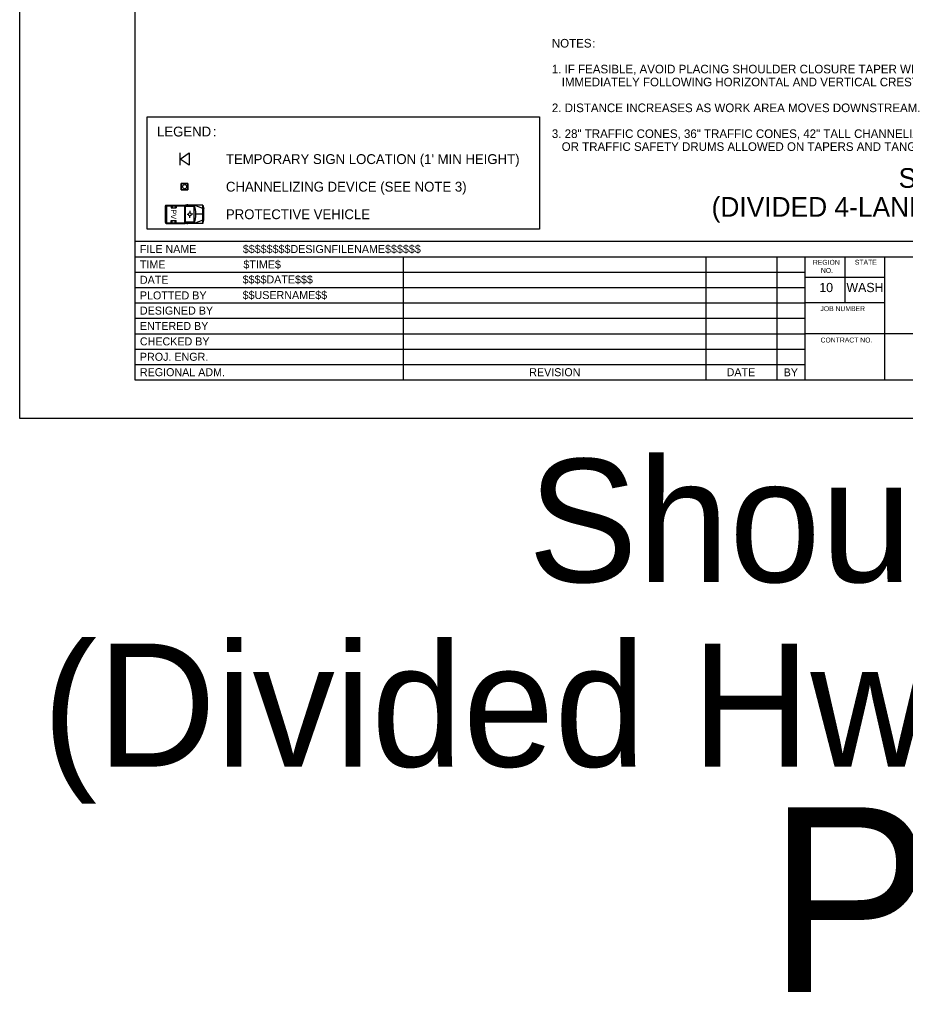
# Model space of a CAD drawing. Extents: x 99999.1 to 100055.7, y 99995 to 100010.7.
# Drawn here: x 99999.06 to 100006.26, y 99995.01 to 100002.93 of the extents above; entities that cross this region are included whole.
import ezdxf

# ---------------------------------------------------------------- set-up
doc = ezdxf.new("R2010")
doc.units = 0
for name, color, linetype in [('SH_DE_DetailHeading1Text', 7, 'Continuous'), ('SH_GI_GeneralNotesBodyText', 7, 'Continuous'), ('SH_GI_PlotLimits', 7, 'Continuous'), ('SH_GI_SheetBorder', 7, 'Continuous'), ('SH_GI_SheetLocationText', 7, 'Continuous'), ('SH_GI_SheetTextInCells', 7, 'Continuous'), ('SH_GI_TitleBlockText', 7, 'Continuous'), ('TR_WZ_PortableSignMountBlk-Wht', 7, 'Continuous'), ('TR_WZ_ProtectiveVehicle', 7, 'Continuous'), ('TR_WZ_TrafficCone', 7, 'Continuous'), ('TR_WZ_WorkZoneTextCurrent', 7, 'Continuous')]:
    doc.layers.add(name, color=color, linetype=linetype)

msp = doc.modelspace()

# ---------------------------------------------------------------- linework, layer by layer
at = {"layer": 'SH_GI_PlotLimits'}
msp.add_lwpolyline([(99999.0625, 99999.6875), (100016.0625, 99999.6875), (100016.0625, 100010.6875), (99999.0625, 100010.6875)], close=True, dxfattribs=at)
at = {"layer": 'SH_GI_SheetBorder'}
for p, q in [((100000, 100010.375), (100000, 100000)), ((100000, 100001.1259), (100015.75, 100001.1259)), ((100000, 100001.0008), (100007.4566, 100001.0008)), ((100002.179, 100001.0008), (100002.179, 100000)), ((100004.641, 100001.0008), (100004.641, 100000)), ((100005.2164, 100001.0008), (100005.2164, 100000)), ((100005.4451, 100001.0008), (100005.4451, 100000)), ((100005.7719, 100000.6255), (100005.7719, 100001.0008)), ((100006.0956, 100000), (100006.0956, 100001.0008)), ((100000, 100000.8757), (100002.1821, 100000.8757)), ((100002.1821, 100000.8757), (100005.4466, 100000.8757)), ((100006.0958, 100000.831), (100005.4466, 100000.831)), ((100000, 100000.7506), (100002.1821, 100000.7506)), ((100002.1821, 100000.7506), (100005.4466, 100000.7506)), ((100000, 100000.6255), (100005.4466, 100000.6255)), ((100006.0958, 100000.6255), (100005.4466, 100000.6255)), ((100000, 100000.5004), (100005.4466, 100000.5004)), ((100000, 100000.3753), (100005.4466, 100000.3753)), ((100007.4566, 100000.3753), (100005.4466, 100000.3753)), ((100000, 100000.2502), (100005.4466, 100000.2502)), ((100000, 100000.1251), (100005.4466, 100000.1251)), ((100000, 100000), (100015.75, 100000))]:
    msp.add_line(p, q, dxfattribs=at)
at = {"layer": 'TR_WZ_PortableSignMountBlk-Wht'}
msp.add_line((100000.3682, 100001.7439), (100000.3682, 100001.8439), dxfattribs=at)
msp.add_lwpolyline([(100000.3682, 100001.7938), (100000.44, 100001.8439), (100000.44, 100001.7439)], close=True, dxfattribs=at)
at = {"layer": 'TR_WZ_ProtectiveVehicle'}
for p, q in [((100000.248, 100001.2779), (100000.248, 100001.4138)), ((100000.2514, 100001.4184), (100000.2547, 100001.4184)), ((100000.2547, 100001.2733), (100000.2547, 100001.4184)), ((100000.2552, 100001.4208), (100000.4095, 100001.4208)), ((100000.2552, 100001.2708), (100000.2552, 100001.4208)), ((100000.2596, 100001.2768), (100000.2596, 100001.4149)), ((100000.2596, 100001.4149), (100000.4052, 100001.4149)), ((100000.2944, 100001.4149), (100000.2944, 100001.3976)), ((100000.2944, 100001.3976), (100000.3356, 100001.3976)), ((100000.3026, 100001.4149), (100000.3026, 100001.3976)), ((100000.3281, 100001.4149), (100000.3281, 100001.3976)), ((100000.3356, 100001.4149), (100000.3356, 100001.3976)), ((100000.4052, 100001.2768), (100000.4052, 100001.4149)), ((100000.4095, 100001.2708), (100000.4095, 100001.4208)), ((100000.4116, 100001.2708), (100000.4116, 100001.4208)), ((100000.5533, 100001.4208), (100000.4116, 100001.4208)), ((100000.4811, 100001.4092), (100000.4116, 100001.4092)), ((100000.4309, 100001.423), (100000.4224, 100001.423)), ((100000.4737, 100001.4092), (100000.4811, 100001.4208)), ((100000.4811, 100001.2708), (100000.4811, 100001.4208)), ((100000.4824, 100001.2708), (100000.4824, 100001.4208)), ((100000.5533, 100001.3934), (100000.4824, 100001.4208)), ((100000.5533, 100001.2708), (100000.5533, 100001.4208)), ((100000.5533, 100001.4208), (100000.5602, 100001.3906)), ((100000.5602, 100001.3011), (100000.5602, 100001.3906)), ((100000.248, 100001.3564), (100000.2547, 100001.3536)), ((100000.248, 100001.3353), (100000.2547, 100001.3381)), ((100000.2498, 100001.3458), (100000.2529, 100001.3458)), ((100000.2514, 100001.3437), (100000.2514, 100001.348)), ((100000.424, 100001.3464), (100000.4352, 100001.3461)), ((100000.4366, 100001.3461), (100000.4366, 100001.3461)), ((100000.4466, 100001.3747), (100000.4468, 100001.3634)), ((100000.4471, 100001.3161), (100000.4471, 100001.3282)), ((100000.4698, 100001.3457), (100000.4603, 100001.3458)), ((100000.5533, 100001.3458), (100000.4963, 100001.3458)), ((100000.5533, 100001.2708), (100000.5602, 100001.3011)), ((100000.2514, 100001.2733), (100000.2547, 100001.2733)), ((100000.2552, 100001.2708), (100000.4095, 100001.2708)), ((100000.2596, 100001.2768), (100000.4052, 100001.2768)), ((100000.2944, 100001.2941), (100000.3356, 100001.2941)), ((100000.2944, 100001.2768), (100000.2944, 100001.2941)), ((100000.3026, 100001.2768), (100000.3026, 100001.2941)), ((100000.3281, 100001.2768), (100000.3281, 100001.2941)), ((100000.3356, 100001.2768), (100000.3356, 100001.2941)), ((100000.4811, 100001.2825), (100000.4116, 100001.2825)), ((100000.5533, 100001.2708), (100000.4116, 100001.2708)), ((100000.4309, 100001.2687), (100000.4224, 100001.2687)), ((100000.4811, 100001.2708), (100000.4721, 100001.2825)), ((100000.5533, 100001.2983), (100000.4824, 100001.2708))]:
    msp.add_line(p, q, dxfattribs=at)
for centre, major_axis, start_param, end_param in [((100000.2514, 100001.4138), (0, 0.00458), 0, 1.570796), ((100000.3812, 100001.3459), (0, 0.1574), 4.215667, 5.208926), ((100000.2514, 100001.2779), (0, -0.00458), 4.712389, 6.283185)]:
    msp.add_ellipse(centre, major_axis=major_axis, ratio=0.73155, start_param=start_param, end_param=end_param, dxfattribs=at)
for centre, major_axis in [((100000.2514, 100001.3458), (0, -0.00211)), ((100000.4471, 100001.3458), (0, -0.0144))]:
    msp.add_ellipse(centre, major_axis=major_axis, ratio=0.73155, dxfattribs=at)
at = {"layer": 'TR_WZ_TrafficCone'}
for points in [[(100000.4308, 100001.5966), (100000.4308, 100001.5432), (100000.3775, 100001.5432), (100000.3775, 100001.5966), (100000.4308, 100001.5966)], [(100000.3775, 100001.5966), (100000.3775, 100001.5432), (100000.4308, 100001.5432), (100000.4308, 100001.5966), (100000.3775, 100001.5966)]]:
    msp.add_lwpolyline(points, dxfattribs=at)
msp.add_circle((100000.4041, 100001.5699), 0.0167, dxfattribs=at)
at = {"layer": 'TR_WZ_WorkZoneTextCurrent'}
msp.add_lwpolyline([(100000.1, 100002.1379), (100003.2886, 100002.1379), (100003.2886, 100001.2259), (100000.1, 100001.2259)], close=True, dxfattribs=at)

# ---------------------------------------------------------------- texts
at = {"layer": 'SH_DE_DetailHeading1Text'}
for s, p in [('SHOULDER CLOSURE', (100006.2068, 100001.5606)), ('(DIVIDED 4-LANE HIGHWAYS, 40 MPH OR LESS)', (100004.6868, 100001.3259))]:
    msp.add_text(s, height=0.16, rotation=360, dxfattribs=at).set_placement(p)
at = {"layer": 'SH_GI_GeneralNotesBodyText'}
for s, p in [('NOTES', (100003.3886, 100002.7006)), (':', (100003.7161, 100002.7006)), ('1. IF FEASIBLE, AVOID PLACING SHOULDER CLOSURE TAPER WITHIN OR ', (100003.3886, 100002.4906)), ('IMMEDIATELY FOLLOWING HORIZONTAL AND VERTICAL CREST CURVES.', (100003.4686, 100002.3856)), ('2. DISTANCE INCREASES AS WORK AREA MOVES DOWNSTREAM.', (100003.3886, 100002.1756)), ('3. 28" TRAFFIC CONES, 36" TRAFFIC CONES, 42" TALL CHANNELIZING DEVICES, ', (100003.3886, 100001.9656)), ('OR TRAFFIC SAFETY DRUMS ALLOWED ON TAPERS AND TANGENTS.', (100003.4686, 100001.8606))]:
    msp.add_text(s, height=0.07, rotation=360, dxfattribs=at).set_placement(p)
at = {"layer": 'SH_GI_SheetLocationText'}
for s, height, p in [('Shoulder Closure', 1, (100003.1945, 99998.3571)), ('(Divided Hwy, 40 mph & Less)', 1, (99999.2479, 99996.8571)), ('Plot 1', 1.5, (100005.1422, 99995.0267))]:
    msp.add_text(s, height=height, dxfattribs=at).set_placement(p)
at = {"layer": 'SH_GI_SheetTextInCells'}
for s, height, p in [('FILE NAME', 0.06505, (100000.041, 100001.0308)), ('TIME', 0.06505, (100000.041, 100000.9057)), ('REGION', 0.04003, (100005.5099, 100000.9352)), ('NO.', 0.04003, (100005.5752, 100000.869)), ('STATE', 0.04003, (100005.8511, 100000.9357)), ('DATE', 0.06505, (100000.041, 100000.7806)), ('10', 0.07506, (100005.5621, 100000.7131)), ('WASH', 0.07506, (100005.7826, 100000.7131)), ('PLOTTED BY', 0.06505, (100000.041, 100000.6538)), ('DESIGNED BY', 0.065052, (100000.041, 100000.5304)), ('JOB NUMBER', 0.04003, (100005.5712, 100000.5587)), ('ENTERED BY', 0.06505, (100000.041, 100000.4053)), ('CHECKED BY', 0.06505, (100000.041, 100000.2802)), ('CONTRACT NO.', 0.040032, (100005.5725, 100000.3037)), ('PROJ. ENGR.', 0.065052, (100000.041, 100000.1551)), ('REGIONAL ADM.', 0.065052, (100000.041, 100000.03)), ('REVISION', 0.06505, (100003.2048, 100000.03)), ('DATE', 0.06505, (100004.8091, 100000.03)), ('BY', 0.06505, (100005.2725, 100000.0285))]:
    msp.add_text(s, height=height, dxfattribs=at).set_placement(p)
at = {"layer": 'SH_GI_TitleBlockText'}
for s, height, p in [('$$$$$$$$DESIGNFILENAME$$$$$$', 0.065052, (100000.8775, 100001.0308)), ('$TIME$', 0.06505, (100000.882, 100000.9059)), ('$$$$DATE$$$', 0.065052, (100000.8759, 100000.7835)), ('$$USERNAME$$', 0.065052, (100000.8759, 100000.6567))]:
    msp.add_text(s, height=height, dxfattribs=at).set_placement(p)
at = {"layer": 'TR_WZ_ProtectiveVehicle'}
msp.add_text('PV', height=0.045, rotation=270, dxfattribs=at).set_placement((100000.2925, 100001.3862))
at = {"layer": 'TR_WZ_WorkZoneTextCurrent'}
for s, p in [('LEGEND', (100000.18, 100001.9779)), (':', (100000.6328, 100001.9779)), ("TEMPORARY SIGN LOCATION (1' MIN HEIGHT)", (100000.74, 100001.7539)), ('CHANNELIZING DEVICE (SEE NOTE 3)', (100000.74, 100001.5299)), ('PROTECTIVE VEHICLE', (100000.74, 100001.3059))]:
    msp.add_text(s, height=0.08, rotation=360, dxfattribs=at).set_placement(p)

doc.saveas('drawing.dxf')
